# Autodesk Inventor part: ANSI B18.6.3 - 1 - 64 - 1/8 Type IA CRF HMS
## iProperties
IsCustomPart: 0
Created: 2008-01
Part Number: ANSI B18.6.3 - 1 - 64 - 1/8 Type IA CRF HMS
Material: Steel, Mild
Description: Cross Recessed Fillister Head Machine Screw - Type IA
Document SubType Name: Modeling
Standard: ANSI B18.6.3
Standard Revision: 2003
Standards Organization: ANSI
Language: en-US
Size Designation: 1 - 64 - 1/8
Categories: <MemberInstance><Categories><Category DisplayName="Fasteners" InternalName="e4da775c-781d-43d5-af7c-5136215cf5a6" Mnemonic="FSTN"><Category DisplayName="Bolts"
Density: 7.86 g/cm^3
Mass: 0.13629 g
Surface Area: 0.464156 cm^2
Volume: 0.0173397 cm^3
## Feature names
1. Body [Revolution]
2. Slot [Extrusion]
3. Cut [Revolution]
4. Star Cut [Extrusion]
5. Fillet1
6. Chamfer
